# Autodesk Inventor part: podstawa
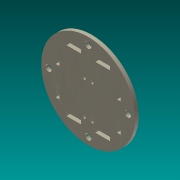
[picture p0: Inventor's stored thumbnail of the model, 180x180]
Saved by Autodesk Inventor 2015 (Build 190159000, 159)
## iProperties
Created: 2016-02
Part Number: podstawa
Material: Generic
Document SubType Name: Modeling
Designer: Rafał
Density: 1 g/cm^3
Appearance: Light Beige
Author: Rafał
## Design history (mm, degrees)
sketch "Sketch1"
  geometry: C1 r 65 at (0, 0); 1 further point
  constraints: 1 centre point, 1 coincident
  dimensions: "d0" = 130 diameter of C1
extrude "Extrusion1" new body sketch "Sketch1" distance "d1" = 5; taper "d2" = 0 deg
sketch "Sketch2" dims "d3" = 90, "d10" = 110
  geometry: L1 (45, 45)-(45, -45); L2 (45, -45)-(-45, -45); L3 (-45, -45)-(-45, 45); L4 (-45, 45)-(45, 45); L5 (-45, 0)-(-45, 10); L6 (-45, 10)-(-40, 10); L7 (-40, 10)-(-40, 30); L8 (-40, 30)-(-45, 30); L9 (-45, 30)-(-45, 10); L10 (0, 45)-(-10, 45); L11 (-45, 0)-(0, 0); L12 (0, 0)-(0, 45); L13 (-10, 45)-(-30, 45); L14 (-30, 45)-(-30, 40); L15 (-30, 40)-(-10, 40); L16 (-10, 40)-(-10, 45); L17 (-40, -10)-(-40, -30); L18 (-40, -30)-(-45, -30); L19 (-45, -30)-(-45, -10); L20 (-45, -10)-(-40, -10); L21 (-30, -45)-(-30, -40); L22 (-10, -45)-(-30, -45); L23 (-10, -40)-(-10, -45); L24 (-30, -40)-(-10, -40); L25 (10, 40)-(10, 45); L26 (10, 45)-(30, 45); L27 (30, 45)-(30, 40); L28 (30, 40)-(10, 40); L29 (40, 30)-(45, 30); L30 (40, 10)-(40, 30); L31 (45, 30)-(45, 10); L32 (45, 10)-(40, 10); L33 (40, -30)-(45, -30); L34 (40, -10)-(40, -30); L35 (45, -10)-(40, -10); L36 (30, -40)-(10, -40); L37 (30, -45)-(30, -40); L38 (10, -40)-(10, -45); L39 (-45, 0)-(-68.355, 0); L40 (10, -40)-(30, -40); L41 (30, -40)-(30, -45); L42 (30, -45)-(10, -45); L43 (10, -45)-(10, -40); L44 (45, -30)-(40, -30); L45 (40, -30)-(40, -10); L46 (40, -10)-(45, -10); L47 (45, -10)-(45, -30); L48 (0, 0)-(0, -12.9); L49 (0, -12.9)-(5.4, -12.9); L50 (0, 0)-(0, 33.9); L51 (0, 33.9)-(5.4, 33.9); C1 r 4.25 at (-55, 0); C2 r 4.25 at (0, -55); C3 r 4.25 at (55, 0); C4 r 4.25 at (0, 55); C5 r 2 at (5.4, -12.9); C6 r 2 at (5.4, 33.9); C7 r 2 at (-5.4, 33.9); C8 r 2 at (-5.4, -12.9); 4 further points
  constraints: 102 end point, 28 symmetric about line, 8 centre point, 8 parallel, 7 coincident, 6 horizontal, 6 perpendicular, 4 point on line, 2 midpoint, 1 horizontal alignment, 1 vertical, 1 vertical alignment, 24 other
  dimensions: "d4" = 10 distance of L5.start L5.end; "d5" = 5 distance of L8.end L7.end; "d6" = 20 distance of L7.end L6.end; "d7" = 10 distance of L10.start L10.end; "d8" = 20 distance of L15.end L14.end; "d9" = 5 distance of L14.end L13.end; "d11" = 8.5 diameter of C1; "d14" = 360 deg dimension on point (0, 0) C1.centre (derived); "d16" = 12.9 distance of L48.start L48.end; "d17" = 5.4 distance of L48.end L49.end; "d18" = 4 diameter of C5; "d19" = 33.9 distance of L48.start L50.end; "d20" = 4 diameter of C6
extrude "Extrusion2" cut sketch "Sketch2" distance "d21" = 10; taper "d22" = 0 deg
body "Solid1"
